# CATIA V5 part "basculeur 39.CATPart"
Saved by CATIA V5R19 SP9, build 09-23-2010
Part number: basculeur 39
Bounding box of the stored display mesh (mm): x -57.798 to -37.798, y -171.144 to -13.385, z -82.404 to 18.408
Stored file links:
  Y:\projet be 2011-12\Etude cinématique\basculeur 39.CATPart
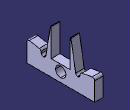
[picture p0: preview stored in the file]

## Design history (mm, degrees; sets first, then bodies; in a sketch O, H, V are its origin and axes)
Body1 (main body)
  DatumSurface1
  DatumPoint1
  DatumPoint2
  Sketch1 on face of DatumSurface1, origin (-57.7977, 0, 0), H (0, -1, 0), V (0, 0, 1)
    line L1 (114.2648, 18.4075) -> (114.2648, -45.3977)
    line L2 (114.2648, -45.3977) -> (92.2648, -45.3977)
    line L3 (92.2648, -45.3977) -> (92.2648, -82.4044)
    line L4 (92.2648, -82.4044) -> (171.1443, -82.4044)
    line L5 (171.1443, -82.4044) -> (171.1443, -33.4852)
    line L6 (138.5378, -39.2346) -> (136.4076, -50.4353)
    line L7 (136.4076, -50.4353) -> (127.5708, -50.4353)
    line L8 (127.5708, -50.4353) -> (116.1198, 18.4075)
    line L9 (116.1198, 18.4075) -> (114.2648, 18.4075)
    line L10 (138.5378, -39.2346) -> (171.1443, -33.4852)
    reference projected point E1 (92.2648, -60.6617) from vertex of DatumPoint1
    reference projected point E2 (92.2648, -60.6617) from vertex of DatumPoint2
    angle L2 L10 = 10
    distance E1 L1 = 22
    horizontal: L2 H, L7 H
    vertical: L3 V, L1 V
    parallelism: L4 L2, L5 L1
    perpendicularity: L9 L1
    coincidence: L3 E2
  Pad1: profile Sketch1, direction (1, 0, 0), length 20
  Plane1: stored without definition
  Plane2: stored without definition
  Sketch2 on start face of Pad1, origin (-57.7977, 0, 0), H (0, -1, 0), V (0, 0, 1)
    circle A1 centre (92.2648, -60.6617) radius 12
    point P1 (92.2648, -60.6617)
    reference intersected line E1 through (92.2648, 0) direction (0, -1) from Plane1
    reference intersected line E2 through (0, -8.6617) direction (-1, 0) from Plane2
    radius A1 = 12
    distance P1 E2 = 52
    coincidence: E1 P1
  Pocket1: profile Sketch2, direction (1, 0, 0), length 20
  Fillet1: radius 5, on edge [face of Pad1 from Sketch1.L7 | face of Pad1 from Sketch1.L8]; edge [face of Pad1 from Sketch1.L6 | face of Pad1 from Sketch1.L7]; edge [face of Pad1 from Sketch1.L10 | face of Pad1 from Sketch1.L6]; edge [face of Pad1 from Sketch1.L5 | face of Pad1 from Sketch1.L10]
  Mirror1: of the body so far, about face of Pad1 from Sketch1.L3
  Sketch3 "point de contact", origin (0, -98.0645, -40.625), H (1, 0, 0), V (0, -0.9863, 0.1652), geometry linked from another document
  Sketch4 on face of Pad1 from Sketch1.L10, origin (0, -10.8869, -61.7429), H (-1, 0, 0), V (0, -0.9848, 0.1736)
    line L1 (47.7977, 156.6875) -> (47.7977, 133.129)
    reference projected point E1 (47.7977, 146.4706) from Sketch3
    vertical: L1 V
    coincidence: E1 L1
